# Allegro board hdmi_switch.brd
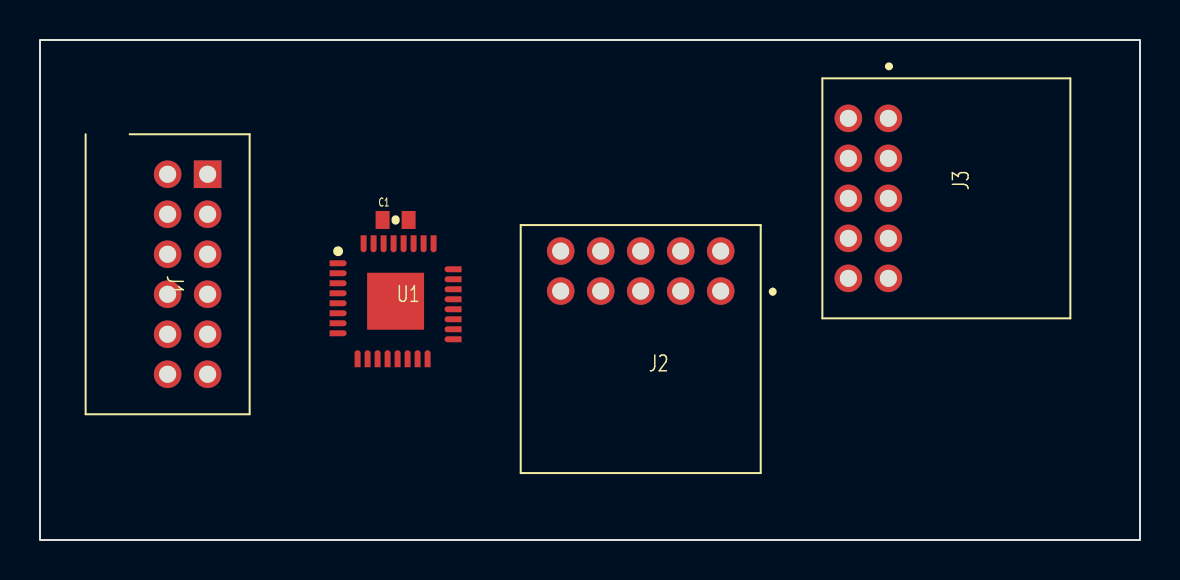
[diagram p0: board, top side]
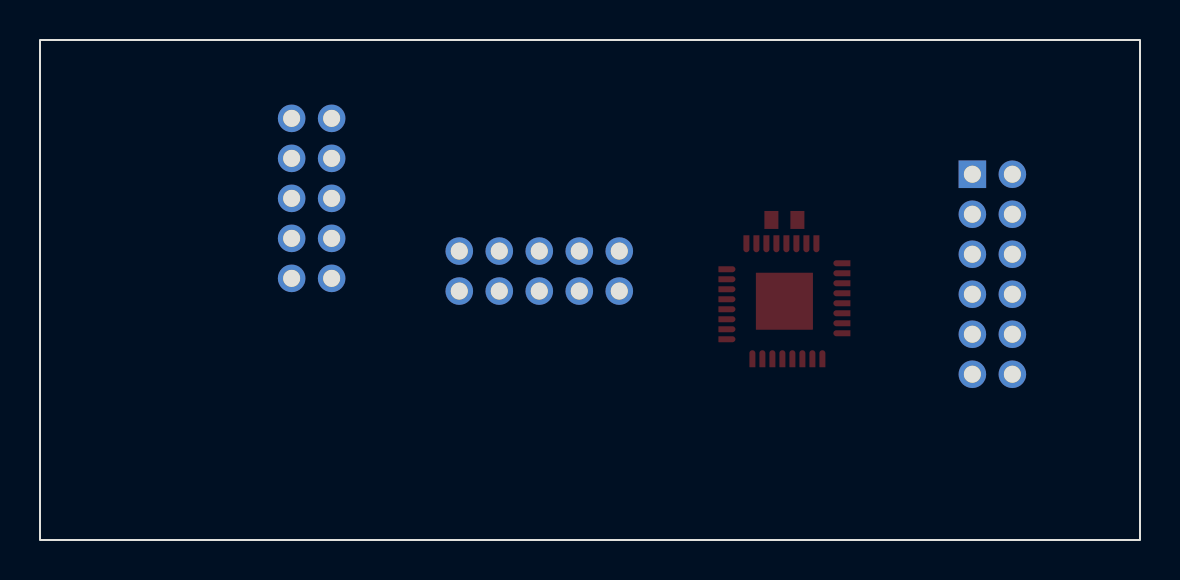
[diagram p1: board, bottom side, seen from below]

Outline 55 x 25 mm; copper layers: TOP, BOTTOM. Coordinates in mm from the lower left corner of the outline.
Outline path: rectangle 0,0 55,25

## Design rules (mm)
constraint set DEFAULT: min track width 0.127

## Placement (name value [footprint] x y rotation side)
C1  100n  [0402-CAP]  17.78 16 0 top
J1  501645-1220  [5016451220]  8.38 18.29 270 top
J2  501876-1040  [5018761040]  34.04 12.45 0 top
J3  501876-1040  [5018761040]  42.42 21.08 90 top
U1  AD8194ACPZ  [QFN50P500X500X100-33N-D]  17.78 11.94 0 top

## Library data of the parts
C1 = CAP NP
J1 = 501645-1220
J2 J3 = 501876-1040
U1 = AD8194ACPZ

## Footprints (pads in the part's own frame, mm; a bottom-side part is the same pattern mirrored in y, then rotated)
0402-CAP
  rect 0.7x0.9 smd: 1(-0.65,0) 2(0.65,0)
5016451220
  round 0 hole 1.4 unplated: (-1.2,-5.1)
  rect 1.381x1.381 hole 0.85: 1(0,0)
  round 1.381 hole 0.85: 2(0,-2) 3(2,0) 4(2,-2) 5(4,0) 6(4,-2) 7(6,0) 8(6,-2) 9(8,0) 10(8,-2) 11(10,0) 12(10,-2)
5018761040
  round 1.381 hole 0.85: 1(0,0) 2(0,2) 3(-2,0) 4(-2,2) 5(-4,0) 6(-4,2) 7(-6,0) 8(-6,2) 9(-8,0) 10(-8,2)
QFN50P500X500X100-33N-D
  custom 0.075x0.075 smd: 1(-2.875,1.9) 2(-2.875,1.4) 3(-2.875,0.9) 4(-2.875,0.4) 5(-2.875,-0.1) 6(-2.875,-0.6) 7(-2.875,-1.1) 8(-2.875,-1.6) 9(-1.9,-2.875) 10(-1.4,-2.875) 11(-0.9,-2.875) 12(-0.4,-2.875) 13(0.1,-2.875) 14(0.6,-2.875) 15(1.1,-2.875) 16(1.6,-2.875) 17(2.875,-1.9) 18(2.875,-1.4) 19(2.875,-0.9) 20(2.875,-0.4) 21(2.875,0.1) 22(2.875,0.6) 23(2.875,1.1) 24(2.875,1.6) 25(1.9,2.875) 26(1.4,2.875) 27(0.9,2.875) 28(0.4,2.875) 29(-0.1,2.875) 30(-0.6,2.875) 31(-1.1,2.875) 32(-1.6,2.875)
  rect 2.85x2.85 smd: 33(0,0)

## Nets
+3.3V: C1.1 J1.1 U1.3 U1.6 U1.14(VTTO) U1.19 U1.22
0: C1.2 J1.3 J2.2 J3.2 U1.11 U1.27 U1.33
HDMI_AUX_0N: J2.3 U1.17
HDMI_AUX_0P: J2.4 U1.18
HDMI_AUX_1N: J2.5 U1.20
HDMI_AUX_1P: J2.6 U1.21
HDMI_AUX_2N: J2.7 U1.23
HDMI_AUX_2P: J2.8 U1.24
HDMI_AUX_3N: J2.9 U1.25
HDMI_AUX_3P: J2.10 U1.26
HDMI_IN_0N: J1.5 U1.28
HDMI_IN_0P: J1.6 U1.29
HDMI_IN_1N: J1.7 U1.31
HDMI_IN_1P: J1.8 U1.32
HDMI_IN_2N: J1.9 U1.1
HDMI_IN_2P: J1.10 U1.2
HDMI_IN_3N: J1.11 U1.4
HDMI_IN_3P: J1.12 U1.5
HDMI_OUT_0N: J3.3 U1.16
HDMI_OUT_0P: J3.4 U1.15
HDMI_OUT_1N: J3.5 U1.13
HDMI_OUT_1P: J3.6 U1.12
HDMI_OUT_2N: J3.7 U1.10
HDMI_OUT_2P: J3.8 U1.9
HDMI_OUT_3N: J3.9 U1.8
HDMI_OUT_3P: J3.10 U1.7
HDMI_SW: J1.4 U1.30

Pads without a net: J1 2; J2 1; J3 1
